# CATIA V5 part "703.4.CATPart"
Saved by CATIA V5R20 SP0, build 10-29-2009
Part number: 703.4
Revision: ANY
Definition: UNKNOWN
Nomenclature: 703.4
Source: Unknown
Bounding box of the stored display mesh (mm): x -40 to 40, y -40 to 40, z 0 to 30
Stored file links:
  C:\Users\Utente\Desktop\IO LAVORO\3D X SITO CF\X 3D SITO CF 27-09-2020\703\703.4.CATPart
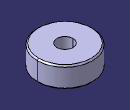
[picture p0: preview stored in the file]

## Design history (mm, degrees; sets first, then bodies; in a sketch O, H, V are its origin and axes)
Body1 "Foro lamato per Vite M12 a testa cilindrica-1" (main body)
  Solid1: solid without history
